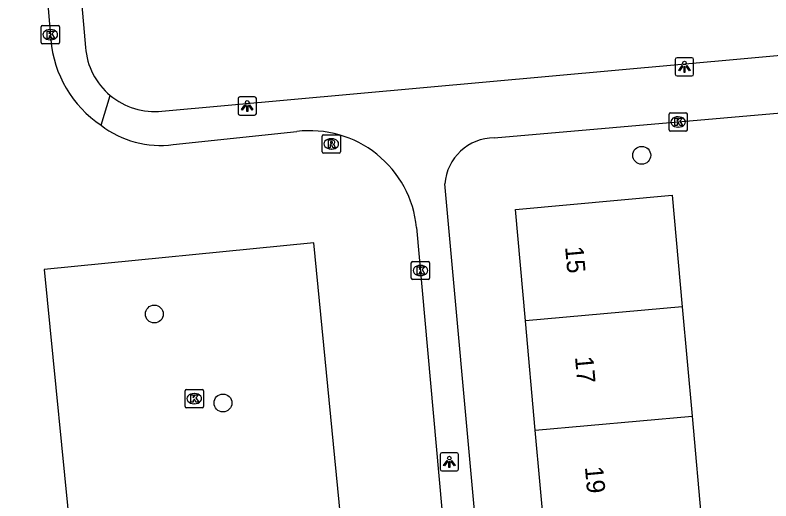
# Model space of a CAD drawing. Extents: x 160557 to 161245, y 385330 to 386505.
# Drawn here: x 161072.59 to 161113.92, y 385547.03 to 385573.59 of the extents above; entities that cross this region are included whole.
import ezdxf

# ---------------------------------------------------------------- set-up
doc = ezdxf.new("R2010")
doc.units = 0
for name, color, linetype in [('IMGEO_Boom', 7, 'Continuous'), ('IMGEO_Kolk', 7, 'Continuous'), ('IMGEO_Lichtpunt', 7, 'Continuous'), ('IMGEO_Pand', 7, 'Continuous'), ('IMGEO_Pand_nummerreeks', 7, 'Continuous'), ('IMGEO_Rijbaan_lokaal_open', 7, 'Continuous'), ('IMGEO_Rioolput', 7, 'Continuous'), ('IMGEO_Voetpad_open', 7, 'Continuous')]:
    doc.layers.add(name, color=color, linetype=linetype)

msp = doc.modelspace()

# ---------------------------------------------------------------- linework, layer by layer
at = {"layer": 'IMGEO_Boom'}
for centre in [(161106.86, 385565.923), (161080.203, 385557.245), (161083.957, 385552.382)]:
    msp.add_circle(centre, 0.489, dxfattribs=at)
at = {"layer": 'IMGEO_Kolk'}
for p, q in [((161074.088, 385573.018), (161074.94, 385573.018)), ((161074.013, 385572.092), (161074.013, 385572.944)), ((161074.501, 385572.798), (161074.526, 385572.798)), ((161075.014, 385572.944), (161075.014, 385572.092)), ((161074.524, 385572.238), (161074.499, 385572.238)), ((161074.94, 385572.018), (161074.088, 385572.018)), ((161108.352, 385567.322), (161108.352, 385568.174)), ((161108.427, 385568.248), (161109.279, 385568.248)), ((161108.84, 385568.028), (161108.865, 385568.028)), ((161109.353, 385568.174), (161109.353, 385567.322)), ((161109.279, 385567.248), (161108.427, 385567.248)), ((161108.863, 385567.468), (161108.838, 385567.468)), ((161094.258, 385559.199), (161094.258, 385560.051)), ((161094.333, 385560.125), (161095.185, 385560.125)), ((161094.746, 385559.905), (161094.771, 385559.905)), ((161095.259, 385560.051), (161095.259, 385559.199)), ((161094.769, 385559.345), (161094.744, 385559.345)), ((161095.185, 385559.125), (161094.333, 385559.125)), ((161081.962, 385553.12), (161082.814, 385553.12)), ((161081.887, 385552.194), (161081.887, 385553.046)), ((161082.375, 385552.9), (161082.4, 385552.9)), ((161082.888, 385553.046), (161082.888, 385552.194)), ((161082.398, 385552.34), (161082.373, 385552.34)), ((161082.814, 385552.12), (161081.962, 385552.12))]:
    msp.add_line(p, q, dxfattribs=at)
for points in [[(161074.088, 385573.018), (161074.94, 385573.018)], [(161074.013, 385572.092), (161074.013, 385572.944)], [(161074.334, 385572.718), (161074.457, 385572.718), (161074.457, 385572.567), (161074.587, 385572.718), (161074.751, 385572.718), (161074.605, 385572.567), (161074.758, 385572.318), (161074.606, 385572.318), (161074.521, 385572.482), (161074.457, 385572.415), (161074.457, 385572.318), (161074.334, 385572.318), (161074.334, 385572.718)], [(161075.014, 385572.944), (161075.014, 385572.092)], [(161074.94, 385572.018), (161074.088, 385572.018)], [(161108.352, 385567.322), (161108.352, 385568.174)], [(161108.427, 385568.248), (161109.279, 385568.248)], [(161109.353, 385568.174), (161109.353, 385567.322)], [(161108.673, 385567.948), (161108.796, 385567.948), (161108.796, 385567.797), (161108.926, 385567.948), (161109.09, 385567.948), (161108.944, 385567.797), (161109.097, 385567.548), (161108.945, 385567.548), (161108.86, 385567.712), (161108.796, 385567.645), (161108.796, 385567.548), (161108.673, 385567.548), (161108.673, 385567.948)], [(161109.279, 385567.248), (161108.427, 385567.248)], [(161094.258, 385559.199), (161094.258, 385560.051)], [(161094.333, 385560.125), (161095.185, 385560.125)], [(161094.579, 385559.825), (161094.702, 385559.825), (161094.702, 385559.674), (161094.832, 385559.825), (161094.996, 385559.825), (161094.85, 385559.674), (161095.003, 385559.425), (161094.851, 385559.425), (161094.766, 385559.589), (161094.702, 385559.522), (161094.702, 385559.425), (161094.579, 385559.425), (161094.579, 385559.825)], [(161095.259, 385560.051), (161095.259, 385559.199)], [(161095.185, 385559.125), (161094.333, 385559.125)], [(161081.962, 385553.12), (161082.814, 385553.12)], [(161081.887, 385552.194), (161081.887, 385553.046)], [(161082.208, 385552.82), (161082.331, 385552.82), (161082.331, 385552.669), (161082.461, 385552.82), (161082.625, 385552.82), (161082.479, 385552.669), (161082.632, 385552.42), (161082.48, 385552.42), (161082.395, 385552.584), (161082.331, 385552.517), (161082.331, 385552.42), (161082.208, 385552.42), (161082.208, 385552.82)], [(161082.888, 385553.046), (161082.888, 385552.194)], [(161082.814, 385552.12), (161081.962, 385552.12)]]:
    msp.add_lwpolyline(points, dxfattribs=at)
for centre, start, end in [((161074.09, 385572.942), 91.552, 178.448), ((161074.09, 385572.942), 91.552, 178.448), ((161074.938, 385572.942), 1.552, 88.448), ((161074.938, 385572.942), 1.552, 88.448), ((161074.09, 385572.094), 181.552, 268.448), ((161074.09, 385572.094), 181.552, 268.448), ((161074.938, 385572.094), 271.552, 358.448), ((161074.938, 385572.094), 271.552, 358.448), ((161108.429, 385568.172), 91.552, 178.448), ((161108.429, 385568.172), 91.552, 178.448), ((161109.277, 385568.172), 1.552, 88.448), ((161109.277, 385568.172), 1.552, 88.448), ((161108.429, 385567.324), 181.552, 268.448), ((161108.429, 385567.324), 181.552, 268.448), ((161109.277, 385567.324), 271.552, 358.448), ((161109.277, 385567.324), 271.552, 358.448), ((161094.335, 385560.049), 91.552, 178.448), ((161094.335, 385560.049), 91.552, 178.448), ((161095.183, 385560.049), 1.552, 88.448), ((161095.183, 385560.049), 1.552, 88.448), ((161094.335, 385559.201), 181.552, 268.448), ((161094.335, 385559.201), 181.552, 268.448), ((161095.183, 385559.201), 271.552, 358.448), ((161095.183, 385559.201), 271.552, 358.448), ((161081.964, 385553.044), 91.552, 178.448), ((161081.964, 385553.044), 91.552, 178.448), ((161082.812, 385553.044), 1.552, 88.448), ((161082.812, 385553.044), 1.552, 88.448), ((161081.964, 385552.196), 181.552, 268.448), ((161081.964, 385552.196), 181.552, 268.448), ((161082.812, 385552.196), 271.552, 358.448), ((161082.812, 385552.196), 271.552, 358.448)]:
    msp.add_arc(centre, 0.0765, start, end, dxfattribs=at)
for centre, major_axis, ratio, start_param, end_param in [((161074.5, 385572.518), (-0.387, 0.002), 0.722429, 4.712389, 7.853982), ((161074.525, 385572.518), (-0.39, 0.002), 0.717154, 1.570796, 4.712389), ((161108.839, 385567.748), (-0.387, 0.002), 0.722429, 4.712389, 7.853982), ((161108.864, 385567.748), (-0.39, 0.002), 0.717154, 1.570796, 4.712389), ((161094.745, 385559.625), (-0.387, 0.002), 0.722429, 4.712389, 7.853982), ((161094.77, 385559.625), (-0.39, 0.002), 0.717154, 1.570796, 4.712389), ((161082.374, 385552.62), (-0.387, 0.002), 0.722429, 4.712389, 7.853982), ((161082.399, 385552.62), (-0.39, 0.002), 0.717154, 1.570796, 4.712389)]:
    msp.add_ellipse(centre, major_axis=major_axis, ratio=ratio, start_param=start_param, end_param=end_param, dxfattribs=at)
at = {"layer": 'IMGEO_Lichtpunt'}
for p, q in [((161108.697, 385571.164), (161108.697, 385570.357)), ((161108.697, 385571.164), (161108.697, 385570.357)), ((161109.599, 385571.259), (161108.791, 385571.259)), ((161109.599, 385571.259), (161108.791, 385571.259)), ((161109.693, 385570.357), (161109.693, 385571.164)), ((161109.693, 385570.357), (161109.693, 385571.164)), ((161108.791, 385570.263), (161109.599, 385570.263)), ((161108.791, 385570.263), (161109.599, 385570.263)), ((161084.786, 385569.021), (161084.786, 385568.214)), ((161084.786, 385569.021), (161084.786, 385568.214)), ((161085.688, 385569.116), (161084.88, 385569.116)), ((161085.688, 385569.116), (161084.88, 385569.116)), ((161085.782, 385568.214), (161085.782, 385569.021)), ((161085.782, 385568.214), (161085.782, 385569.021)), ((161084.88, 385568.12), (161085.688, 385568.12)), ((161084.88, 385568.12), (161085.688, 385568.12)), ((161095.839, 385549.57), (161095.839, 385548.763)), ((161095.839, 385549.57), (161095.839, 385548.763)), ((161096.741, 385549.665), (161095.933, 385549.665)), ((161096.741, 385549.665), (161095.933, 385549.665)), ((161096.835, 385548.763), (161096.835, 385549.57)), ((161096.835, 385548.763), (161096.835, 385549.57)), ((161095.933, 385548.669), (161096.741, 385548.669)), ((161095.933, 385548.669), (161096.741, 385548.669))]:
    msp.add_line(p, q, dxfattribs=at)
for points in [[(161109.071, 385570.828), (161109.11, 385570.8), (161108.922, 385570.538), (161108.884, 385570.565), (161109.071, 385570.828)], [(161109.173, 385570.78), (161109.22, 385570.78), (161109.22, 385570.458), (161109.173, 385570.458), (161109.173, 385570.78)], [(161109.283, 385570.8), (161109.321, 385570.827), (161109.508, 385570.565), (161109.469, 385570.537), (161109.283, 385570.8)], [(161085.16, 385568.685), (161085.199, 385568.657), (161085.011, 385568.395), (161084.973, 385568.422), (161085.16, 385568.685)], [(161085.262, 385568.637), (161085.309, 385568.637), (161085.309, 385568.315), (161085.262, 385568.315), (161085.262, 385568.637)], [(161085.372, 385568.657), (161085.41, 385568.684), (161085.597, 385568.422), (161085.558, 385568.394), (161085.372, 385568.657)], [(161096.213, 385549.234), (161096.252, 385549.206), (161096.064, 385548.944), (161096.026, 385548.971), (161096.213, 385549.234)], [(161096.315, 385549.186), (161096.362, 385549.186), (161096.362, 385548.864), (161096.315, 385548.864), (161096.315, 385549.186)], [(161096.425, 385549.206), (161096.463, 385549.233), (161096.65, 385548.971), (161096.611, 385548.943), (161096.425, 385549.206)]]:
    msp.add_lwpolyline(points, dxfattribs=at)
for centre in [(161109.196, 385570.962), (161085.285, 385568.819), (161096.338, 385549.368)]:
    msp.add_circle(centre, 0.0994, dxfattribs=at)
for centre, start, end in [((161108.791, 385571.164), 90, 180), ((161108.791, 385571.164), 90, 180), ((161109.599, 385571.164), 0, 90), ((161109.599, 385571.164), 0, 90), ((161108.791, 385570.357), 180, 270), ((161108.791, 385570.357), 180, 270), ((161109.599, 385570.357), 270, 0), ((161109.599, 385570.357), 270, 360), ((161084.88, 385569.021), 90, 180), ((161084.88, 385569.021), 90, 180), ((161085.688, 385569.021), 0, 90), ((161085.688, 385569.021), 0, 90), ((161084.88, 385568.214), 180, 270), ((161084.88, 385568.214), 180, 270), ((161085.688, 385568.214), 270, 0), ((161085.688, 385568.214), 270, 360), ((161095.933, 385549.57), 90, 180), ((161095.933, 385549.57), 90, 180), ((161096.741, 385549.57), 0, 90), ((161096.741, 385549.57), 0, 90), ((161095.933, 385548.763), 180, 270), ((161095.933, 385548.763), 180, 270), ((161096.741, 385548.763), 270, 0), ((161096.741, 385548.763), 270, 360)]:
    msp.add_arc(centre, 0.0946, start, end, dxfattribs=at)
at = {"layer": 'IMGEO_Pand'}
for points in [[(161100.499, 385556.867), (161099.949, 385562.964), (161108.527, 385563.737), (161109.077, 385557.641)], [(161109.077, 385557.641), (161100.499, 385556.867)], [(161109.077, 385557.641), (161109.616, 385551.664)], [(161101.038, 385550.89), (161100.499, 385556.867)], [(161101.038, 385550.89), (161109.616, 385551.664)], [(161109.616, 385551.664), (161110.154, 385545.687)], [(161101.577, 385544.913), (161101.038, 385550.89)]]:
    msp.add_lwpolyline(points, dxfattribs=at)
at = {"layer": 'IMGEO_Rijbaan_lokaal_open'}
for points in [[(161070.591, 385618.12), (161070.675, 385617.407), (161070.927, 385614.424), (161074.538, 385572.239)], [(161081.239, 385566.506), (161087.997, 385567.225)], [(161094.547, 385561.983), (161097.451, 385529.564)], [(161092.075, 385528.866), (161088.931, 385561.144), (161074.182, 385559.689), (161077.358, 385527.606), (161077.377, 385527.415), (161092.075, 385528.866)]]:
    msp.add_lwpolyline(points, dxfattribs=at)
for centre, radius, start, end in [((161080.8, 385572.774), 6.284, 184.8847, 236.0174), ((161080.546, 385571.831), 5.37, 232.6352, 277.4172), ((161088.706, 385561.398), 5.87, 5.7201, 96.9389)]:
    msp.add_arc(centre, radius, start, end, dxfattribs=at)
at = {"layer": 'IMGEO_Rioolput'}
for p, q in [((161089.381, 385566.12), (161089.381, 385566.972)), ((161089.456, 385567.046), (161090.308, 385567.046)), ((161089.869, 385566.826), (161089.894, 385566.826)), ((161090.382, 385566.972), (161090.382, 385566.12)), ((161090.308, 385566.046), (161089.456, 385566.046)), ((161089.892, 385566.266), (161089.867, 385566.266))]:
    msp.add_line(p, q, dxfattribs=at)
for points in [[(161089.381, 385566.12), (161089.381, 385566.972)], [(161089.456, 385567.046), (161090.308, 385567.046)], [(161090.382, 385566.972), (161090.382, 385566.12)], [(161089.97, 385566.744), (161089.718, 385566.746), (161089.718, 385566.346)], [(161089.718, 385566.346), (161089.842, 385566.346), (161089.842, 385566.508), (161089.853, 385566.508)], [(161089.896, 385566.665), (161089.842, 385566.665), (161089.842, 385566.584)], [(161089.842, 385566.584), (161089.894, 385566.584)], [(161089.9, 385566.479), (161089.971, 385566.346), (161090.111, 385566.346), (161090.046, 385566.472)], [(161090.308, 385566.046), (161089.456, 385566.046)]]:
    msp.add_lwpolyline(points, dxfattribs=at)
for centre, radius, start, end in [((161089.458, 385566.97), 0.0765, 91.552, 178.448), ((161089.458, 385566.97), 0.0765, 91.552, 178.448), ((161090.306, 385566.97), 0.0765, 1.552, 88.448), ((161090.306, 385566.97), 0.0765, 1.552, 88.448), ((161089.852, 385566.455), 0.0533, 26.0293, 88.6989), ((161089.878, 385566.773), 0.19, 274.7715, 282.9687), ((161089.902, 385566.569), 0.0964, 77.0061, 93.1865), ((161089.916, 385566.626), 0.0378, 276.6634, 79.6772), ((161089.969, 385566.634), 0.109, 350.3612, 89.416), ((161089.967, 385566.634), 0.112, 277.5842, 350.9817), ((161089.951, 385566.419), 0.108, 29.5134, 73.7905), ((161089.458, 385566.122), 0.0765, 181.552, 268.448), ((161089.458, 385566.122), 0.0765, 181.552, 268.448), ((161090.306, 385566.122), 0.0765, 271.552, 358.448), ((161090.306, 385566.122), 0.0765, 271.552, 358.448)]:
    msp.add_arc(centre, radius, start, end, dxfattribs=at)
for centre, major_axis, ratio, start_param, end_param in [((161089.868, 385566.546), (-0.387, 0.002), 0.722429, 4.712389, 7.853982), ((161089.893, 385566.546), (-0.39, 0.002), 0.717154, 1.570796, 4.712389)]:
    msp.add_ellipse(centre, major_axis=major_axis, ratio=ratio, start_param=start_param, end_param=end_param, dxfattribs=at)
at = {"layer": 'IMGEO_Voetpad_open'}
for points in [[(161074.681, 385591.873), (161076.441, 385571.826)], [(161080.619, 385568.341), (161123.151, 385572.178)], [(161077.287, 385567.563), (161077.79, 385569.197)], [(161098.796, 385566.874), (161117.833, 385568.528)], [(161099.576, 385526.035), (161096.096, 385564.364)]]:
    msp.add_lwpolyline(points, dxfattribs=at)
for centre, radius, start, end in [((161080.21, 385572.099), 3.779, 184.1501, 230.1767), ((161080.212, 385572.097), 3.778, 230.1407, 276.1898), ((161098.792, 385564.171), 2.703, 89.9158, 175.907)]:
    msp.add_arc(centre, radius, start, end, dxfattribs=at)

# ---------------------------------------------------------------- texts
at = {"layer": 'IMGEO_Pand_nummerreeks'}
for s, p in [('15', (161102.665, 385560.914)), ('17', (161103.207, 385554.897)), ('19', (161103.75, 385548.88))]:
    msp.add_text(s, height=1, rotation=275.1521, dxfattribs=at).set_placement(p)

doc.saveas('drawing.dxf')
